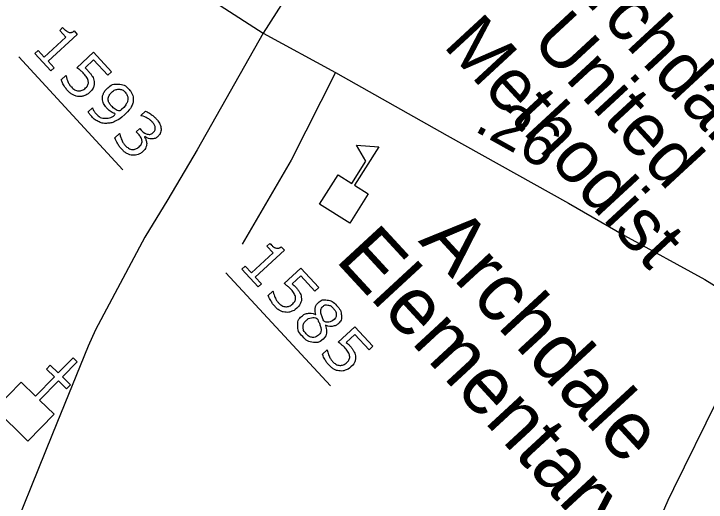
# Model space of a CAD drawing. Extents: x 1695041 to 1706254, y 786537 to 798223.
# Drawn here: x 1703183.7 to 1703274.6, y 796476 to 796540 of the extents above; entities that cross this region are included whole.
import ezdxf

# ---------------------------------------------------------------- set-up
doc = ezdxf.new("R2010")
doc.units = 0
for name, color, linetype in [('Default', 7, 'Continuous'), ('Old_Level_29', 7, 'Continuous'), ('Old_Level_32', 7, 'Continuous')]:
    doc.layers.add(name, color=color, linetype=linetype)

msp = doc.modelspace()

# ---------------------------------------------------------------- linework, layer by layer
at = {"layer": 'Default'}
for p, q in [((1703184.389, 796534.335), (1703198.057, 796519.528)), ((1703211.571, 796506.045), (1703225.265, 796491.21))]:
    msp.add_line(p, q, dxfattribs=at)
for points in [[(1703188.599, 796532.499), (1703186.479, 796534.796), (1703186.912, 796535.195), (1703187.728, 796534.312), (1703190.572, 796536.937), (1703189.756, 796537.821), (1703190.144, 796538.179)], [(1703191.649, 796537.737), (1703192.057, 796537.295), (1703188.233, 796533.765), (1703189.032, 796532.899), (1703188.599, 796532.499)], [(1703192.016, 796532.925), (1703194.202, 796534.943), (1703196.559, 796532.39), (1703196.06, 796531.93), (1703194.209, 796533.935), (1703193.081, 796532.894)], [(1703189.947, 796531.355), (1703190.548, 796531.91), (1703190.585, 796531.87)], [(1703225.929, 796532.291), (1703220.116, 796520.784), (1703213.681, 796509.788)], [(1703193.507, 796527.147), (1703194.055, 796527.652), (1703194.081, 796527.624)], [(1703200.444, 796526.631), (1703200.418, 796526.66), (1703201.013, 796527.209)], [(1703200.045, 796524.248), (1703199.808, 796524.505), (1703200.279, 796524.94), (1703200.463, 796524.74)], [(1703197.012, 796523.741), (1703197.607, 796524.29), (1703197.647, 796524.247)], [(1703200.921, 796523.886), (1703200.881, 796523.85)], [(1703215.781, 796504.208), (1703213.661, 796506.505), (1703214.094, 796506.905), (1703214.909, 796506.022), (1703217.753, 796508.647), (1703216.938, 796509.53), (1703217.326, 796509.888)], [(1703218.831, 796509.446), (1703219.239, 796509.004), (1703215.415, 796505.474), (1703216.214, 796504.608), (1703215.781, 796504.208)], [(1703219.198, 796504.635), (1703221.384, 796506.653), (1703223.741, 796504.1), (1703223.242, 796503.639), (1703221.39, 796505.645), (1703220.263, 796504.604)], [(1703217.129, 796503.065), (1703217.73, 796503.619), (1703217.767, 796503.58)], [(1703223.339, 796500.567), (1703223.356, 796500.583)], [(1703224.635, 796499.151), (1703224.618, 796499.135)], [(1703226.298, 796496.943), (1703228.484, 796498.961), (1703230.841, 796496.408), (1703230.342, 796495.947), (1703228.49, 796497.953), (1703227.362, 796496.912)], [(1703224.229, 796495.373), (1703224.83, 796495.928), (1703224.866, 796495.888)]]:
    msp.add_lwpolyline(points, dxfattribs=at)
for points in [[(1703223.862, 796515.049), (1703226.274, 796518.877), (1703228.073, 796517.743), (1703229.922, 796520.678), (1703228.681, 796522.784), (1703231.614, 796522.53), (1703228.448, 796517.507), (1703230.248, 796516.373), (1703227.836, 796512.545)], [(1703184.716, 796491.719), (1703186.595, 796489.879), (1703189.061, 796492.387), (1703188.007, 796493.424), (1703188.524, 796493.95), (1703189.578, 796492.914), (1703191.526, 796494.895), (1703192.054, 796494.376), (1703190.106, 796492.395), (1703191.161, 796491.358), (1703190.643, 796490.832), (1703189.589, 796491.868), (1703187.123, 796489.36), (1703189.019, 796487.489), (1703185.571, 796483.982), (1703181.268, 796488.212)]]:
    msp.add_lwpolyline(points, close=True, dxfattribs=at)
for points in [[(1703190.144, 796538.179), (1703190.31, 796537.999), (1703190.529, 796537.822), (1703190.748, 796537.644), (1703190.903, 796537.591), (1703191.095, 796537.526), (1703191.274, 796537.551), (1703191.454, 796537.577), (1703191.649, 796537.737)], [(1703190.585, 796531.87), (1703190.652, 796531.499), (1703190.837, 796531.09), (1703191.022, 796530.68), (1703191.301, 796530.378), (1703191.488, 796530.176), (1703191.72, 796530.039), (1703191.952, 796529.902), (1703192.232, 796529.886), (1703192.47, 796529.874), (1703192.701, 796529.968), (1703192.932, 796530.062), (1703193.157, 796530.27), (1703193.377, 796530.473), (1703193.459, 796530.688), (1703193.541, 796530.904), (1703193.508, 796531.122), (1703193.48, 796531.37), (1703193.329, 796531.623), (1703193.177, 796531.876), (1703192.935, 796532.138), (1703192.704, 796532.389), (1703192.455, 796532.589), (1703192.206, 796532.789), (1703192.016, 796532.925)], [(1703193.081, 796532.894), (1703193.205, 796532.782), (1703193.33, 796532.659), (1703193.454, 796532.536), (1703193.541, 796532.442), (1703193.859, 796532.097), (1703194.04, 796531.783), (1703194.221, 796531.47), (1703194.273, 796531.116), (1703194.327, 796530.743), (1703194.194, 796530.389), (1703194.062, 796530.034), (1703193.688, 796529.689)], [(1703193.688, 796529.689), (1703193.392, 796529.415), (1703193.021, 796529.273), (1703192.65, 796529.132), (1703192.291, 796529.149), (1703191.902, 796529.169), (1703191.533, 796529.354), (1703191.164, 796529.539), (1703190.82, 796529.912), (1703190.499, 796530.26), (1703190.274, 796530.649), (1703190.05, 796531.038), (1703189.947, 796531.355)], [(1703194.081, 796527.624), (1703194.114, 796527.501), (1703194.214, 796527.314), (1703194.314, 796527.127), (1703194.485, 796526.942), (1703195.066, 796526.313), (1703195.773, 796526.304), (1703196.481, 796526.296), (1703197.197, 796526.852), (1703196.793, 796526.969), (1703196.509, 796527.139), (1703196.225, 796527.309), (1703195.97, 796527.585), (1703195.729, 796527.847), (1703195.584, 796528.107), (1703195.44, 796528.366), (1703195.391, 796528.716), (1703195.334, 796529.128), (1703195.486, 796529.502), (1703195.637, 796529.876), (1703196.011, 796530.221), (1703196.662, 796530.822), (1703197.464, 796530.771), (1703198.267, 796530.72), (1703198.835, 796530.105), (1703199.119, 796529.797), (1703199.265, 796529.447), (1703199.412, 796529.096), (1703199.402, 796528.723), (1703199.389, 796528.262), (1703199.138, 796527.788), (1703198.886, 796527.313), (1703198.296, 796526.768)], [(1703197.886, 796527.461), (1703198.328, 796527.869), (1703198.512, 796528.208), (1703198.696, 796528.546), (1703198.697, 796528.842), (1703198.702, 796529.094), (1703198.616, 796529.299), (1703198.53, 796529.504), (1703198.364, 796529.683), (1703197.986, 796530.093), (1703197.51, 796530.094), (1703197.034, 796530.095), (1703196.57, 796529.666), (1703196.299, 796529.416), (1703196.199, 796529.181), (1703196.099, 796528.946), (1703196.139, 796528.646), (1703196.168, 796528.436), (1703196.28, 796528.255), (1703196.392, 796528.074), (1703196.565, 796527.886), (1703196.77, 796527.664), (1703197.04, 796527.492), (1703197.31, 796527.319), (1703197.608, 796527.226), (1703197.671, 796527.278), (1703197.733, 796527.328), (1703197.795, 796527.377), (1703197.886, 796527.461)], [(1703198.296, 796526.768), (1703197.739, 796526.254), (1703197.169, 796525.962), (1703196.598, 796525.67), (1703196.041, 796525.632), (1703195.477, 796525.591), (1703194.939, 796525.818), (1703194.402, 796526.046), (1703193.915, 796526.573), (1703193.778, 796526.721), (1703193.673, 796526.867), (1703193.568, 796527.013), (1703193.507, 796527.147)], [(1703200.463, 796524.74), (1703200.864, 796524.307), (1703201.283, 796524.216), (1703201.703, 796524.125), (1703202.052, 796524.447), (1703202.206, 796524.589), (1703202.261, 796524.761), (1703202.316, 796524.934), (1703202.282, 796525.119), (1703202.243, 796525.311), (1703202.143, 796525.477), (1703202.042, 796525.643), (1703201.879, 796525.82), (1703201.629, 796526.091), (1703201.25, 796526.307), (1703200.871, 796526.523), (1703200.444, 796526.631)], [(1703201.013, 796527.209), (1703201.299, 796527.098), (1703201.695, 796526.838), (1703202.091, 796526.577), (1703202.384, 796526.26), (1703202.671, 796525.949), (1703202.832, 796525.66), (1703202.994, 796525.37), (1703203.045, 796525.064), (1703203.098, 796524.732), (1703203.001, 796524.447), (1703202.905, 796524.163), (1703202.645, 796523.923), (1703202.292, 796523.597), (1703201.797, 796523.603), (1703201.303, 796523.61), (1703200.921, 796523.886)], [(1703201.17, 796522.981), (1703201.173, 796522.731), (1703201.07, 796522.472), (1703200.966, 796522.212), (1703200.672, 796521.941), (1703200.381, 796521.672), (1703200.041, 796521.554), (1703199.701, 796521.436), (1703199.345, 796521.461), (1703198.948, 796521.49), (1703198.586, 796521.691), (1703198.223, 796521.892), (1703197.905, 796522.237), (1703197.579, 796522.59), (1703197.347, 796523.01), (1703197.115, 796523.429), (1703197.012, 796523.741)], [(1703197.647, 796524.247), (1703197.711, 796523.857), (1703197.908, 796523.432), (1703198.106, 796523.006), (1703198.388, 796522.701), (1703198.554, 796522.521), (1703198.801, 796522.374), (1703199.048, 796522.227), (1703199.281, 796522.209), (1703199.528, 796522.194), (1703199.738, 796522.27), (1703199.949, 796522.345), (1703200.181, 796522.559), (1703200.409, 796522.77), (1703200.492, 796522.981), (1703200.575, 796523.193), (1703200.542, 796523.4), (1703200.512, 796523.611), (1703200.376, 796523.824), (1703200.24, 796524.037), (1703200.045, 796524.248)], [(1703200.881, 796523.85), (1703200.984, 796523.692), (1703201.075, 796523.448), (1703201.165, 796523.204), (1703201.17, 796522.981)], [(1703217.326, 796509.888), (1703217.492, 796509.709), (1703217.711, 796509.531), (1703217.93, 796509.354), (1703218.085, 796509.301), (1703218.277, 796509.235), (1703218.456, 796509.261), (1703218.635, 796509.287), (1703218.831, 796509.446)], [(1703217.767, 796503.58), (1703217.834, 796503.209), (1703218.019, 796502.799), (1703218.204, 796502.389), (1703218.483, 796502.087), (1703218.67, 796501.885), (1703218.902, 796501.748), (1703219.134, 796501.612), (1703219.414, 796501.595), (1703219.652, 796501.583), (1703219.883, 796501.677), (1703220.113, 796501.771), (1703220.339, 796501.98), (1703220.559, 796502.183), (1703220.641, 796502.398), (1703220.722, 796502.613), (1703220.69, 796502.831), (1703220.662, 796503.08), (1703220.511, 796503.333), (1703220.359, 796503.586), (1703220.117, 796503.848), (1703219.886, 796504.099), (1703219.637, 796504.299), (1703219.388, 796504.499), (1703219.198, 796504.635)], [(1703220.263, 796504.604), (1703220.387, 796504.492), (1703220.511, 796504.369), (1703220.636, 796504.245), (1703220.722, 796504.151), (1703221.041, 796503.806), (1703221.222, 796503.493), (1703221.403, 796503.179), (1703221.455, 796502.826), (1703221.509, 796502.453), (1703221.376, 796502.098), (1703221.244, 796501.744), (1703220.87, 796501.399)], [(1703220.87, 796501.399), (1703220.574, 796501.125), (1703220.203, 796500.983), (1703219.832, 796500.841), (1703219.473, 796500.858), (1703219.084, 796500.879), (1703218.715, 796501.064), (1703218.346, 796501.249), (1703218.002, 796501.622), (1703217.681, 796501.97), (1703217.456, 796502.359), (1703217.231, 796502.748), (1703217.129, 796503.065)], [(1703223.356, 796500.583), (1703223.222, 796501.093), (1703223.287, 796501.457), (1703223.352, 796501.821), (1703223.677, 796502.121), (1703224.156, 796502.563), (1703224.838, 796502.464), (1703225.521, 796502.366), (1703226.081, 796501.758), (1703226.668, 796501.123), (1703226.713, 796500.462), (1703226.759, 796499.801), (1703226.288, 796499.367), (1703226, 796499.101), (1703225.557, 796499.025), (1703225.113, 796498.948), (1703224.635, 796499.151)], [(1703225.764, 796499.923), (1703226.069, 796500.204), (1703226.033, 796500.607), (1703225.996, 796501.009), (1703225.659, 796501.375), (1703225.327, 796501.734), (1703224.944, 796501.806), (1703224.561, 796501.878), (1703224.27, 796501.61), (1703224.065, 796501.421), (1703224.022, 796501.167), (1703223.979, 796500.913), (1703224.078, 796500.572), (1703224.124, 796500.419), (1703224.225, 796500.144), (1703224.325, 796499.869), (1703224.445, 796499.631), (1703224.894, 796499.522), (1703225.197, 796499.6), (1703225.499, 796499.678), (1703225.764, 796499.923)], [(1703224.316, 796497.335), (1703223.766, 796496.827), (1703223.005, 796496.92), (1703222.244, 796497.012), (1703221.644, 796497.662), (1703221.007, 796498.352), (1703220.985, 796499.09), (1703220.964, 796499.829), (1703221.52, 796500.342), (1703221.873, 796500.668), (1703222.349, 796500.727), (1703222.825, 796500.785), (1703223.339, 796500.567)], [(1703223.722, 796497.871), (1703223.984, 796498.113), (1703224.036, 796498.374), (1703224.087, 796498.636), (1703223.936, 796499.12), (1703223.875, 796499.312), (1703223.781, 796499.522), (1703223.688, 796499.731), (1703223.54, 796500.086), (1703223.164, 796500.213), (1703222.781, 796500.148), (1703222.399, 796500.082), (1703222.097, 796499.803), (1703221.713, 796499.448), (1703221.707, 796498.952), (1703221.701, 796498.455), (1703222.077, 796498.048), (1703222.462, 796497.631), (1703222.905, 796497.579), (1703223.349, 796497.527), (1703223.722, 796497.871)], [(1703224.618, 796499.135), (1703224.816, 796498.578), (1703224.76, 796498.135), (1703224.704, 796497.693), (1703224.316, 796497.335)], [(1703224.866, 796495.888), (1703224.934, 796495.517), (1703225.119, 796495.107), (1703225.304, 796494.698), (1703225.583, 796494.396), (1703225.77, 796494.193), (1703226.002, 796494.057), (1703226.234, 796493.92), (1703226.513, 796493.903), (1703226.752, 796493.892), (1703226.983, 796493.986), (1703227.213, 796494.08), (1703227.439, 796494.288), (1703227.659, 796494.491), (1703227.741, 796494.706), (1703227.822, 796494.922), (1703227.79, 796495.14), (1703227.762, 796495.388), (1703227.611, 796495.641), (1703227.459, 796495.894), (1703227.217, 796496.156), (1703226.986, 796496.407), (1703226.737, 796496.607), (1703226.488, 796496.807), (1703226.298, 796496.943)], [(1703227.362, 796496.912), (1703227.487, 796496.8), (1703227.611, 796496.677), (1703227.735, 796496.554), (1703227.822, 796496.46), (1703228.141, 796496.115), (1703228.322, 796495.801), (1703228.503, 796495.488), (1703228.555, 796495.134), (1703228.609, 796494.761), (1703228.476, 796494.406), (1703228.344, 796494.052), (1703227.97, 796493.707)], [(1703227.97, 796493.707), (1703227.674, 796493.433), (1703227.303, 796493.291), (1703226.932, 796493.15), (1703226.573, 796493.166), (1703226.184, 796493.187), (1703225.815, 796493.372), (1703225.446, 796493.557), (1703225.102, 796493.93), (1703224.781, 796494.278), (1703224.556, 796494.667), (1703224.331, 796495.056), (1703224.229, 796495.373)]]:
    msp.add_open_spline(points, degree=3, dxfattribs=at)
at = {"layer": 'Old_Level_29'}
for points in [[(1703104.127, 796531.913), (1703117.881, 796533.946), (1703133.1, 796536.122), (1703155.07, 796539.162), (1703169.572, 796541.41), (1703176.301, 796542.48), (1703187.744, 796544.386), (1703190.804, 796544.619), (1703195.343, 796544.81), (1703199.039, 796544.367), (1703202.955, 796543.84), (1703206.699, 796542.726), (1703210.792, 796541.078), (1703216.472, 796537.44)], [(1703216.472, 796537.44), (1703225.929, 796532.291)], [(1703225.929, 796532.291), (1703240.583, 796524.02), (1703256.493, 796515.144), (1703263.876, 796510.908), (1703274.383, 796505.158), (1703278.66, 796502.537), (1703280.446, 796501.588), (1703281.596, 796500.651)], [(1703250.984, 796413.283), (1703251.071, 796415.221), (1703253.921, 796427.155), (1703260.642, 796453.426), (1703262.543, 796460.036), (1703269.586, 796476.248), (1703270.317, 796477.779), (1703281.596, 796500.651)]]:
    msp.add_lwpolyline(points, dxfattribs=at)
at = {"layer": 'Old_Level_32'}
for points in [[(1703242.257, 796579.448), (1703237.376, 796572.077), (1703231.914, 796563.75), (1703229.444, 796559.919), (1703220.862, 796544.418), (1703216.472, 796537.44)], [(1703216.472, 796537.44), (1703207.811, 796522.163), (1703203.937, 796515.641), (1703200.926, 796510.726), (1703194.446, 796498.572), (1703193.506, 796496.418), (1703188.808, 796484.942), (1703182.204, 796468.564), (1703178.325, 796460.501), (1703176.018, 796454.732), (1703175.806, 796454.26)]]:
    msp.add_lwpolyline(points, dxfattribs=at)

# ---------------------------------------------------------------- texts
at = {"layer": 'Default'}
for s, height, rotation, p in [('Archdale', 6.93, 312.70907, (1703254.512, 796545.995)), ('United ', 6.93, 312.70907, (1703251.447, 796536.305)), ('Methodist', 6.93, 312.70907, (1703239.94, 796535.761)), ('.26', 5.775, 330.84351, (1703243.974, 796524.732)), ('Archdale', 7.623, 312.70907, (1703236.72, 796510.163)), ('Elementary', 7.623, 312.70907, (1703225.798, 796507.685))]:
    msp.add_text(s, height=height, rotation=rotation, dxfattribs=at).set_placement(p)

doc.saveas('drawing.dxf')
